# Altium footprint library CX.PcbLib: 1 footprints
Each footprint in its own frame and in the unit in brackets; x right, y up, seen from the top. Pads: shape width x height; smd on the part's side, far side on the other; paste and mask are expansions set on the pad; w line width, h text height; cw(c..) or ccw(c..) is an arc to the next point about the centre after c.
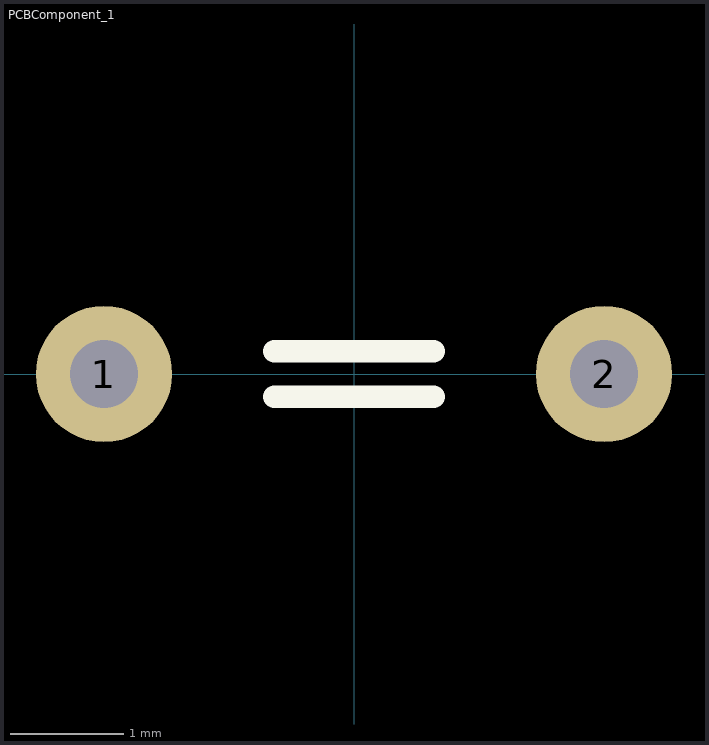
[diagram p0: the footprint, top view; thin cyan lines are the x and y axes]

## PCBComponent_1 [mm]
pads (2):
  round 1.2 hole 0.6: 1(-2.2,0) 2(2.2,0)
Top Overlay:
  lines w0.2: -0.7,-0.2 0.7,-0.2 ; -0.7,0.2 0.7,0.2
M5 Assembly Top:
  text ".Designator" at -2,-0.7 h1.85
